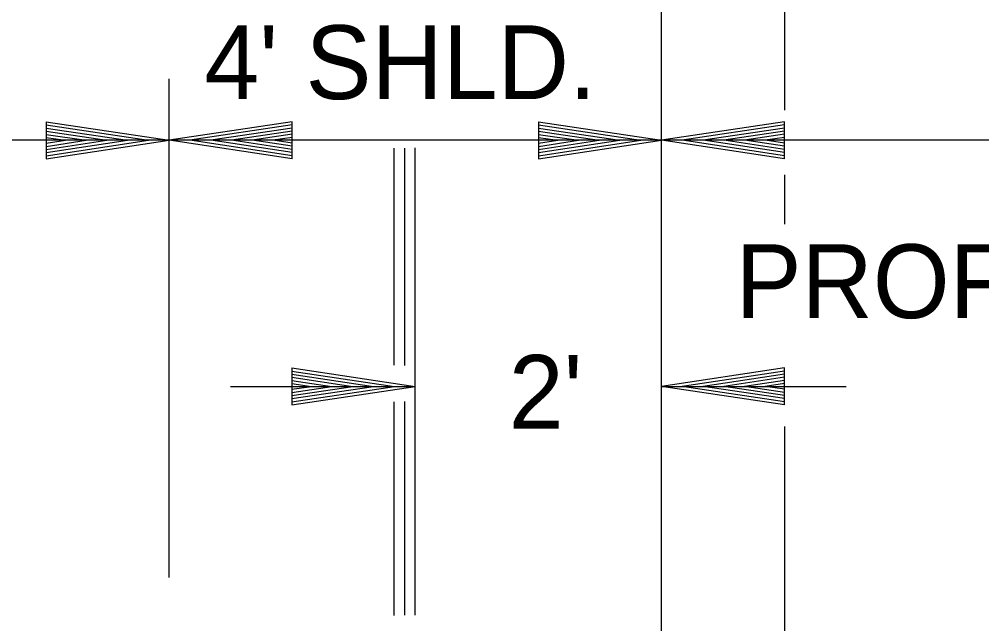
# Model space of a CAD drawing. Extents: x 2478 to 3210, y 439 to 841.
# Drawn here: x 2995.95 to 3011.59, y 598.27 to 608.09 of the extents above; entities that cross this region are included whole.
import ezdxf

# ---------------------------------------------------------------- set-up
doc = ezdxf.new("R2010")
doc.units = 0
doc.layers.add('R_Annotation', color=7, linetype='Continuous')
doc.layers.add('R_Dimension', color=7, linetype='Continuous')

msp = doc.modelspace()

# ---------------------------------------------------------------- linework, layer by layer
at = {"layer": 'R_Dimension'}
for p, q in [((3006.387, 597.232), (3006.387, 611.675)), ((3008.387, 610.625), (3008.387, 606.614)), ((2998.387, 599.019), (2998.387, 607.125)), ((2996.387, 606.425), (2998.387, 606.125)), ((2996.387, 606.425), (2996.387, 605.825)), ((2996.387, 606.375), (2998.053, 606.125)), ((3000.387, 606.425), (2998.387, 606.125)), ((3000.387, 606.375), (2998.721, 606.125)), ((3000.387, 605.825), (3000.387, 606.425)), ((3004.387, 606.425), (3006.387, 606.125)), ((3004.387, 606.425), (3004.387, 605.825)), ((3004.387, 606.375), (3006.053, 606.125)), ((3008.387, 606.425), (3006.387, 606.125)), ((3008.387, 606.375), (3006.721, 606.125)), ((3008.387, 605.825), (3008.387, 606.425)), ((2996.387, 606.324), (2997.709, 606.125)), ((2996.387, 606.274), (2997.376, 606.125)), ((2996.387, 606.222), (2997.037, 606.125)), ((3000.387, 606.324), (2999.065, 606.125)), ((3000.387, 606.274), (2999.398, 606.125)), ((3000.387, 606.223), (2999.737, 606.125)), ((3004.387, 606.324), (3005.709, 606.125)), ((3004.387, 606.274), (3005.376, 606.125)), ((3004.387, 606.222), (3005.037, 606.125)), ((3008.387, 606.324), (3007.065, 606.125)), ((3008.387, 606.274), (3007.398, 606.125)), ((3008.387, 606.223), (3007.737, 606.125)), ((3067.845, 606.125), (2988.928, 606.125)), ((2996.387, 606.172), (2996.703, 606.125)), ((2996.387, 605.825), (2998.387, 606.125)), ((2996.387, 606.027), (2997.037, 606.125)), ((2996.387, 605.926), (2997.709, 606.125)), ((2996.387, 605.875), (2998.053, 606.125)), ((2996.387, 605.976), (2997.376, 606.125)), ((2996.387, 606.078), (2996.703, 606.125)), ((3000.387, 605.825), (2998.387, 606.125)), ((3000.387, 605.875), (2998.721, 606.125)), ((3000.387, 605.926), (2999.065, 606.125)), ((3000.387, 605.976), (2999.398, 606.125)), ((3000.387, 606.028), (2999.737, 606.125)), ((3000.387, 606.172), (3000.071, 606.125)), ((3000.387, 606.078), (3000.071, 606.125)), ((3004.387, 606.172), (3004.703, 606.125)), ((3004.387, 605.825), (3006.387, 606.125)), ((3004.387, 606.027), (3005.037, 606.125)), ((3004.387, 605.926), (3005.709, 606.125)), ((3004.387, 605.875), (3006.053, 606.125)), ((3004.387, 605.976), (3005.376, 606.125)), ((3004.387, 606.078), (3004.703, 606.125)), ((3008.387, 605.825), (3006.387, 606.125)), ((3008.387, 605.875), (3006.721, 606.125)), ((3008.387, 605.926), (3007.065, 606.125)), ((3008.387, 605.976), (3007.398, 606.125)), ((3008.387, 606.028), (3007.737, 606.125)), ((3008.387, 606.172), (3008.071, 606.125)), ((3008.387, 606.078), (3008.071, 606.125)), ((3002.045, 602.47), (3002.045, 605.995)), ((3002.216, 602.465), (3002.216, 605.995)), ((3002.383, 598.409), (3002.383, 606.003)), ((3008.387, 605.563), (3008.387, 604.764)), ((3000.383, 602.425), (3002.383, 602.125)), ((3000.383, 602.425), (3000.383, 601.825)), ((3000.383, 602.375), (3002.049, 602.125)), ((3000.383, 602.324), (3001.705, 602.125)), ((3008.387, 602.425), (3006.387, 602.125)), ((3008.387, 602.375), (3006.721, 602.125)), ((3008.387, 602.324), (3007.065, 602.125)), ((3008.387, 601.825), (3008.387, 602.425)), ((3000.383, 602.274), (3001.372, 602.125)), ((3000.383, 602.222), (3001.033, 602.125)), ((3000.383, 602.172), (3000.699, 602.125)), ((3008.387, 602.274), (3007.398, 602.125)), ((3008.387, 602.223), (3007.737, 602.125)), ((3008.387, 602.172), (3008.071, 602.125)), ((2999.383, 602.125), (3002.383, 602.125)), ((3000.383, 601.825), (3002.383, 602.125)), ((3000.383, 602.027), (3001.033, 602.125)), ((3000.383, 601.926), (3001.705, 602.125)), ((3000.383, 601.875), (3002.049, 602.125)), ((3000.383, 601.976), (3001.372, 602.125)), ((3000.383, 602.078), (3000.699, 602.125)), ((3008.387, 601.825), (3006.387, 602.125)), ((3006.387, 602.125), (3009.387, 602.125)), ((3008.387, 601.875), (3006.721, 602.125)), ((3008.387, 601.926), (3007.065, 602.125)), ((3008.387, 601.976), (3007.398, 602.125)), ((3008.387, 602.028), (3007.737, 602.125)), ((3008.387, 602.078), (3008.071, 602.125)), ((3002.045, 598.401), (3002.045, 601.876)), ((3002.216, 598.409), (3002.216, 601.881)), ((3008.387, 601.475), (3008.387, 597.28))]:
    msp.add_line(p, q, dxfattribs=at)

# ---------------------------------------------------------------- texts
at = {"layer": 'R_Annotation'}
for s, p in [("4' SHLD.", (2998.959, 606.795)), ('PROFILE GRADE', (3007.592, 603.235)), ("2'", (3003.905, 601.436))]:
    msp.add_text(s, height=1.2, dxfattribs=at).set_placement(p)

doc.saveas('drawing.dxf')
